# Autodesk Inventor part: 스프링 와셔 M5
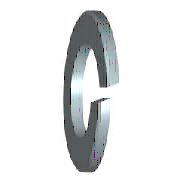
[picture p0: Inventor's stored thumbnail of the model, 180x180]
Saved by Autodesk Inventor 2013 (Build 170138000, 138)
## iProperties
IsCustomPart: 1
Created: 2012-02
Part Number: 스프링 와셔 M5
Material: 강철, 연강
Description: 스프링 와셔
Document SubType Name: Modeling
Standard: JIS B 1251
Designer: mdu-01
Standards Organization: JIS
Language: ko-KR
Size Designation: 번호 2 5
Categories: <MemberInstance><Categories><Category DisplayName="조임쇠" InternalName="e4da775c-781d-43d5-af7c-5136215cf5a6" Mnemonic="FSTN"><Category DisplayName="와셔" InternalN
Density: 1 g/cm^3
Author: mdu-01
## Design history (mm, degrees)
sketch "스케치1"
  geometry: C1 r 4.6 at (0, 0); C2 r 2.55 at (0, 0); 1 further point
  constraints: 2 centre point, 2 coincident
  dimensions: "d0" = 5.1 diameter of C2 (= SD1); "d1" = 9.2 diameter of C1 (= SD2)
extrude "본체" new body sketch "스케치1" distance "d2" = 1.3 (= SD); taper "d3" = 0 deg
sketch "스케치2"
  geometry: L1 (0, -2.55)-(0, 2.55) reference; L2 (1.3, 4.6)-(1.3, -4.6) reference; L3 (-1.2, 0)-(7.2, 0) reference; L4 (0, -0.26)-(1.3, 0.213); L5 (0, 0.26)-(1.3, 0.733)
  constraints: 4 end point, 4 point on line, 1 parallel
  dimensions: "d4" = 0.26 distance from line of L3 L4.start (= 0.2 x SD); "d5" = 0.26 distance from line of L3 L5.start (= 0.2 x SD); "d6" = 70 deg angle of L2 L4 (= FAWI)
extrude "절단부" cut sketch "스케치2" stored distance "d7" = 1.3 (= SD); taper "d8" = 0 deg
workaxis "Work Axis1"
workplane "Work Plane1"
body "Solid1"
other parameters: "SD1" = 5.1 [user parameter; used in 1 equation term], "SD2" = 9.2 [user parameter; used in 1 equation term], "SD" = 1.3 [user parameter; used in 4 equation terms], "FAWI" = 70 deg [user parameter; used in 1 equation term], "d9" = 0, "d10" = 0, "d11" = 0, "d12" = 0, "SDI" = 1.7 [user parameter], "NND" = 5 [user parameter]
